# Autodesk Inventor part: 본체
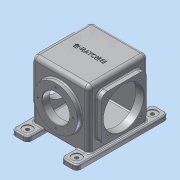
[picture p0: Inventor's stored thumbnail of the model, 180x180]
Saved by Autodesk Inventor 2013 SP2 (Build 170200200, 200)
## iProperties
Created: 2026-01
Part Number: 본체
Material: 알루미늄 6061
Document SubType Name: Modeling
Designer: a
Density: 2.71 g/cm^3
Mass: 2728.19 g
Surface Area: 2458.75 cm^2
Volume: 1006.71 cm^3
Author: a
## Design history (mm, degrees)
sketch "스케치1"
  geometry: L1 (-71, -74)-(71, -74); L2 (71, -74)-(71, 74); L3 (71, 74)-(-71, 74); L4 (-71, 74)-(-71, -74); L5 (-71, -74)-(71, 74); L6 (71, -74)-(-71, 74); 1 further point
  constraints: 12 end point, 2 midpoint, 2 parallel, 1 horizontal, 1 perpendicular
  dimensions: "d0" = 142 distance of L3.end L2.end; "d1" = 148 distance of L2.end L1.end
extrude "돌출1" new body sketch "스케치1" stored distance "d2" = 148; taper "d3" = 0 deg
feature "쉘1" dims "d4" = 7
fillet "모깎기1" dims "d5" = 10
node "작업 평면1"
sketch "스케치2"
  geometry: L1 (-41, 56)-(41, 56); L2 (56, 41)-(56, -41); L3 (41, -56)-(-41, -56); L4 (-56, -41)-(-56, 41); L5 (-56, 56)-(56, -56); L6 (56, 56)-(-56, -56); C1 r 50 at (0, 0); A1 r 15 centre (41, 41) between (56, 41) and (41, 56); A2 r 15 centre (41, -41) between (41, -56) and (56, -41); A3 r 15 centre (-41, -41) between (-56, -41) and (-41, -56); A4 r 15 centre (-41, 41) between (-41, 56) and (-56, 41); 1 further point
  constraints: 12 end point, 8 point on circle, 8 point on line, 8 tangent, 5 centre point, 3 equal radius, 2 midpoint, 2 parallel, 1 coincident, 1 horizontal, 1 perpendicular
  dimensions: "d8" = 112 distance of L5.end L6.end; "d9" = 112 distance of L6.start L5.end; "d10" = 15 radius of A1; "d13" = 100 diameter of C1
extrude "돌출2" join sketch "스케치2" stored distance "d11" = 148; taper "d12" = 0 deg
extrude "돌출3" cut sketch "스케치2" stored distance "d14" = 148; taper "d15" = 0 deg
sketch "스케치3"
  geometry: L1 (-41, -41)-(41, -41); L2 (41, -41)-(41, 41); L3 (41, 41)-(-41, 41); L4 (-41, 41)-(-41, -41); L5 (-41, -41)-(41, 41); L6 (41, -41)-(-41, 41); C1 r 50 at (0, 0) reference; A1 r 15 centre (41, 41) between (56, 41) and (41, 56) reference; 4 further points
  constraints: 12 end point, 4 coincident, 2 midpoint, 2 parallel, 1 horizontal, 1 perpendicular
  dimensions: "d16" = 82 distance of L3.end L2.end (derived); "d17" = 82 distance of L2.end L1.end (derived)
hole "구멍1" sketch "스케치3" at (-41, 41), (41, 41), (41, -41), (-41, -41) diameter "d18" = 4.917; stored, may be unused: countersink angle "d22" = 90 deg, drill point angle "d24" = 118 deg; dims "d19" = 12, "d20" = 4, "d21" = 2, "d23" = 14
fillet "모깎기3" dims "d25" = 3
fillet "모깎기4" dims "d26" = 10
node "작업 평면2"
sketch "스케치4"
  geometry: C1 r 54 at (0, 0); 1 further point
  constraints: 1 centre point, 1 coincident
  dimensions: "d28" = 108 diameter of C1
extrude "돌출4" join sketch "스케치4" stored distance "d29" = 10; taper "d30" = 0 deg
sketch "스케치5"
  geometry: C1 r 54 at (0, 0) reference; C2 r 34 at (0, 0)
  constraints: 1 centre point, 1 coincident
  dimensions: "d31" = 68 diameter of C2
extrude "돌출5" cut sketch "스케치5" stored distance "d32" = 10; taper "d33" = 0 deg
fillet "모깎기5" dims "d34" = 3
fillet "모깎기6" dims "d35" = 3
sketch "스케치6"
  geometry: C1 r 34 at (0, 0) reference; 1 further point
  constraints: 1 vertical alignment
  dimensions: "d36" = 44 distance of C1.centre point (0, 44)
hole "구멍2" sketch "스케치6" at (0, 44) diameter "d37" = 4.917; stored, may be unused: countersink angle "d41" = 90 deg, drill point angle "d43" = 118 deg; dims "d38" = 12, "d39" = 4, "d40" = 2, "d42" = 14
fillet "모깎기7" dims "d47" = 3
sketch "스케치7"
  geometry: L1 (-81, -70)-(-41, -70); L2 (-41, -70)-(-41, -82); L3 (-41, -82)-(-81, -82); L4 (-81, -82)-(-81, -70); L5 (-81, -70)-(-41, -82); L6 (-41, -70)-(-81, -82); L7 (61, -74)-(-61, -74) reference; 2 further points
  constraints: 12 end point, 2 midpoint, 2 parallel, 1 horizontal, 1 perpendicular
  dimensions: "d48" = 40 distance of L2.end L3.end; "d49" = 12 distance of L1.end L2.end; "d50" = 8 distance between parallel lines of L7 L3; "d51" = 81 distance from line of point (0, 0) L4
extrude "돌출6" join sketch "스케치7" stored distance "d52" = 228; taper "d53" = 0 deg
fillet "모깎기8" dims "d54" = 10
fillet "모깎기9" dims "d55" = 3
sketch "스케치8"
  geometry: 3 further points
  constraints: 1 vertical alignment
  dimensions: "d58" = 61 horizontal distance of point (71, -111) point (10, -17); "d59" = 188 distance of point (10, -205) point (10, -17); "d60" = 94 vertical distance of point (71, -111) point (10, -17)
hole "구멍3" sketch "스케치8" at (10, -17), (10, -205) diameter "d61" = 9; stored, may be unused: countersink angle "d65" = 90 deg, drill point angle "d67" = 118 deg; dims "d62" = 12, "d63" = 24, "d64" = 2, "d66" = 14
fillet "모깎기12" dims "d68" = 3
fillet "모깎기13" dims "d69" = 3
chamfer "모따기1" distance "d70" = 1; stored, may be unused: second distance "d71" = 2, angle "d72" = 45 deg
sketch "스케치9"
  geometry: 2 further points
  constraints: 1 coincident, 1 other
feature "엠보싱1" sketch "스케치9" dims "d0" = 142, "d1" = 148, "d8" = 112, "d9" = 112, "d10" = 15, "d73" = 0.5, "d74" = 0
node "솔리드1"
mirror "대칭1"
pattern_circular "원형 패턴1" dims angle "d45" = 360 deg
mirror "대칭2"
other parameters: "d7" = 84, "d27" = 11
